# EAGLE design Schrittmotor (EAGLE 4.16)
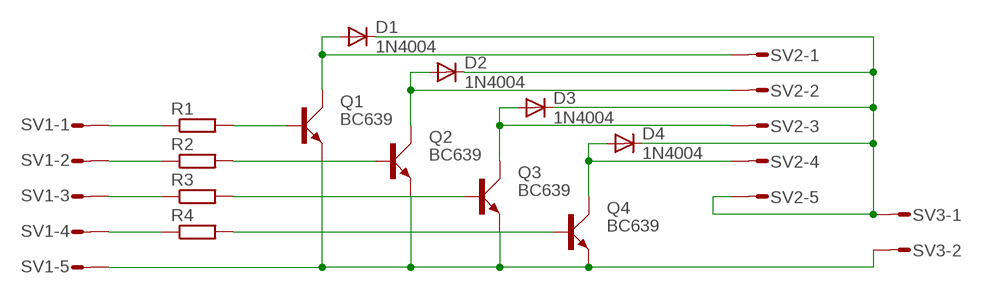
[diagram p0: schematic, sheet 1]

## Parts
D1  1N4004  [DO41-10]
D2  1N4004  [DO41-10]
D3  1N4004  [DO41-10]
D4  1N4004  [DO41-10]
Q1  BC639  [SOT54D]
Q2  BC639  [SOT54D]
Q3  BC639  [SOT54D]
Q4  BC639  [SOT54D]
R1  R-EU_0204/7  [0204/7]
R2  R-EU_0204/7  [0204/7]
R3  R-EU_0204/7  [0204/7]
R4  R-EU_0204/7  [0204/7]
SV1  L05P  [L05P]
SV2  L05P  [L05P]
SV3  L02P  [L02P]

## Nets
GND: Q1.E Q2.E Q3.E Q4.E SV1.5 SV3.2
N$1: R1.1 SV1.1
N$2: R2.1 SV1.2
N$3: R3.1 SV1.3
N$4: R4.1 SV1.4
N$5: Q1.B R1.2
N$7: Q2.B R2.2
N$9: Q3.B R3.2
N$11: Q4.B R4.2
N$12: D1.A Q1.C SV2.1
N$13: D2.A Q2.C SV2.2
N$14: D3.A Q3.C SV2.3
N$15: D4.A Q4.C SV2.4
UF: D1.C D2.C D3.C D4.C SV2.5 SV3.1

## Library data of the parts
D1-D4 = diode:1N4004: DIODE
Q1-Q4 = transistor-small-signal:BC639: NPN TRANSISTOR
R1-R4 = rcl:R-EU_: RESISTOR, European symbol
SV1 SV2 = con-amp-mt:L05P: AMP MT CONNECTOR
SV3 = con-amp-mt:L02P: AMP MT CONNECTOR

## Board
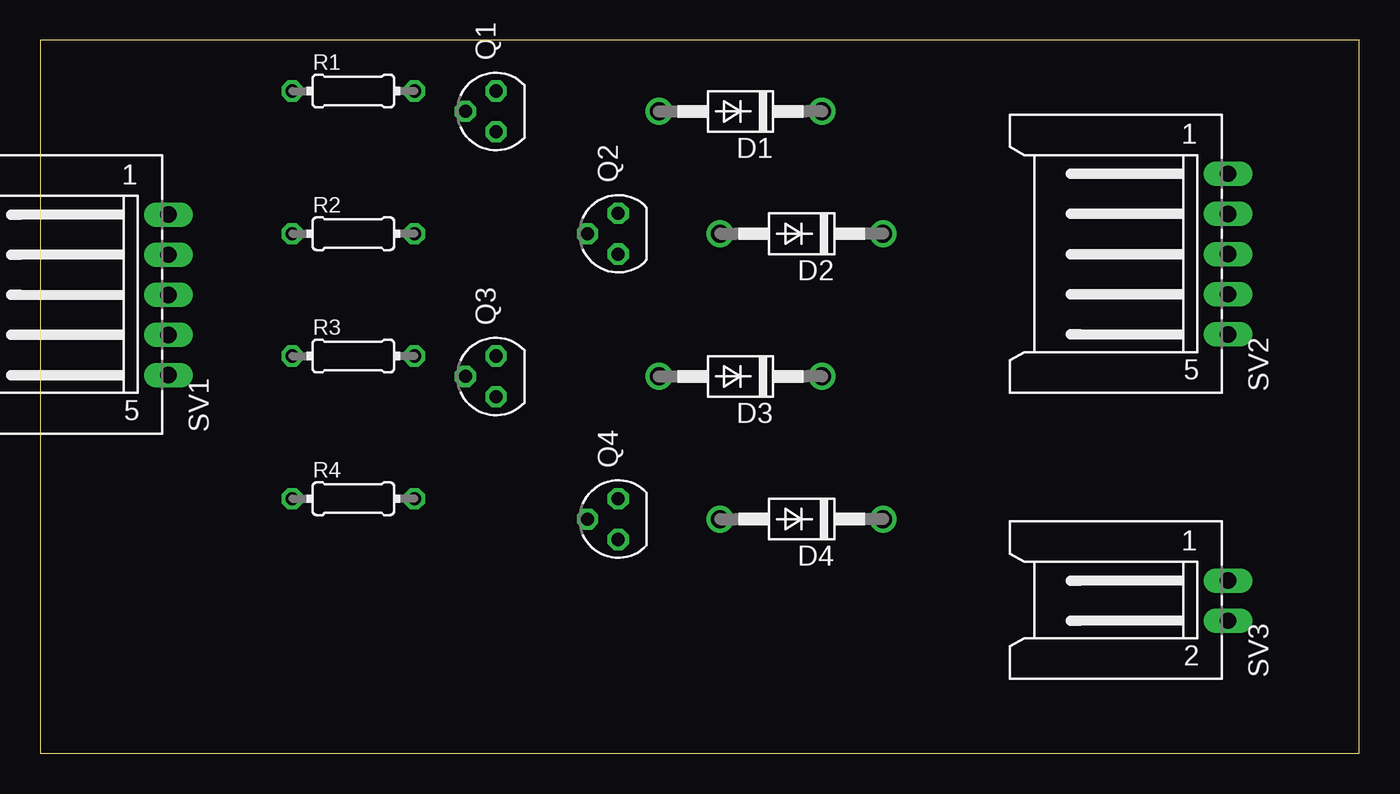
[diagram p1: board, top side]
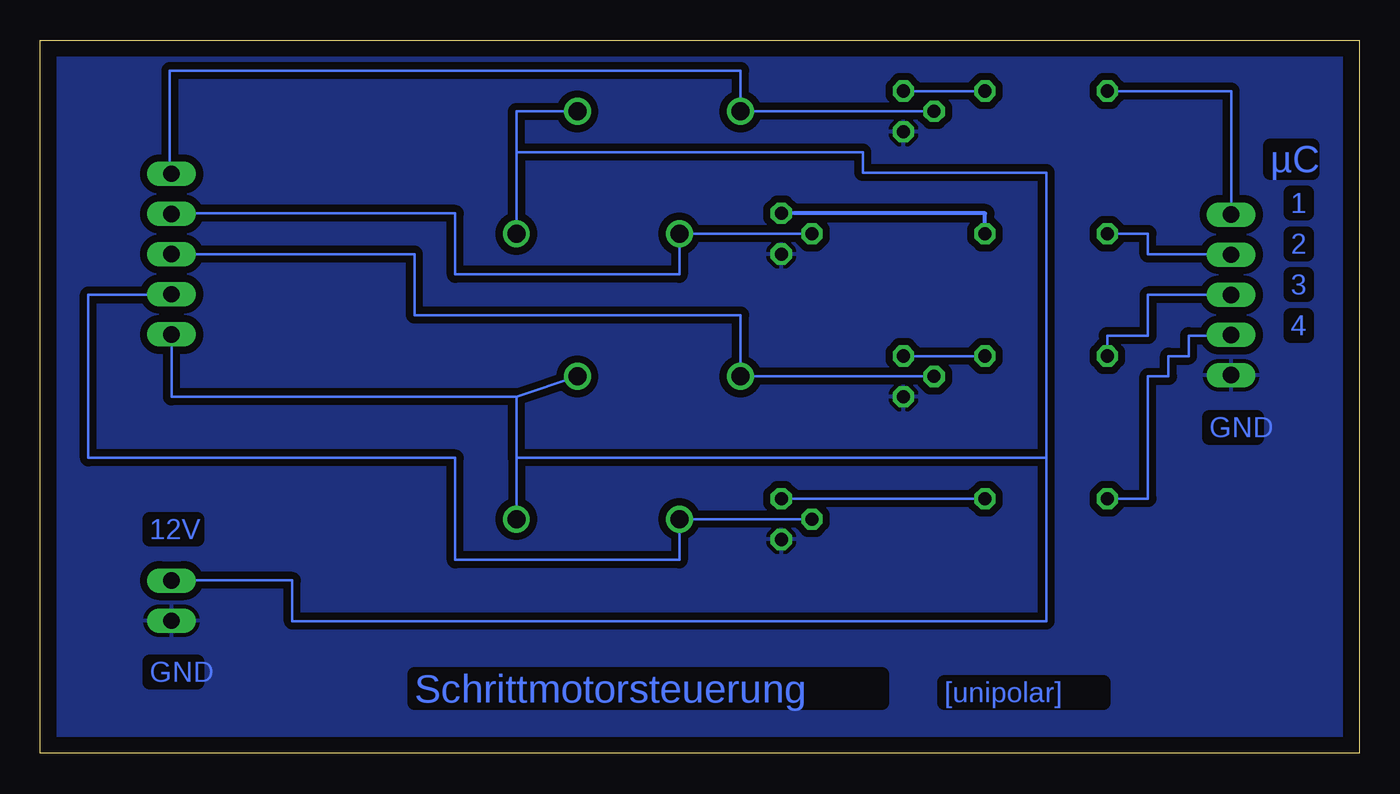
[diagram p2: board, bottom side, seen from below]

Size 82.22 x 44.44 mm. Coordinates in mm from the lower left corner, seen from the top.
Outline: 0,0 82.22,0 82.22,44.44 0,44.44 0,0
Copper layers (1*16): Top 0.035mm / dielectric 1.5mm / Bottom 0.035mm
Design rules "default": minimum track width 10mil, minimum drill 24mil, track to track 18mil, track to pad 18mil, pad to pad 10mil, via to via 10mil, smd to smd 8mil, copper to edge 40mil, drill to drill 8mil, minimum pad ring 10mil, minimum via ring 8mil, stop-mask expansion 4mil, vias tented up to drill 0mil, thermal gap 10mil

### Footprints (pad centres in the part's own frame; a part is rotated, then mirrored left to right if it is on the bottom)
DO41-10 = drill 1.118 round: A 5.08,0; C -5.08,0
SOT54D = drill 0.813 octagon: B 1.27,0; C 0,1.905; E -1.27,0
0204/7 = drill 0.813 octagon: 1 -3.81,0; 2 3.81,0
L05P = drill 1.016 long: 1 5,-6.25; 2 2.5,-6.25; 3 0,-6.25; 4 -2.5,-6.25; 5 -5,-6.25
L02P = drill 1.016 long: 1 1.25,-6.25; 2 -1.25,-6.25

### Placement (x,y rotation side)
D1  43.65,40 180 top
D2  47.46,32.38 180 top
D3  43.65,23.49 180 top
D4  47.46,14.6 180 top
Q1  28.41,40 90 top
Q2  36.03,32.38 90 top
Q3  28.41,23.49 90 top
Q4  36.03,14.6 90 top
R1  19.52,41.27 0 top
R2  19.52,32.38 0 top
R3  19.52,24.76 0 top
R4  19.52,15.87 0 top
SV1  1.74,28.57 90 top
SV2  67.78,31.11 90 top
SV3  67.78,9.52 90 top

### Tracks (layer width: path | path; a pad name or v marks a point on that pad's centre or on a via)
GND
  pour Bottom: -0.8,45.08 -0.8,-0.64 83.02,-0.64 83.02,45.08
N$1
  Bottom 0.152: SV1.1 7.99,41.27 R1.1
N$2
  Bottom 0.152: 7.99,31.11 13.17,31.11 13.17,32.38 R2.1
  Bottom 0.254: SV1.2 7.99,31.11
N$3
  Bottom 0.152: SV1.3 13.17,28.57 13.17,26.03 15.71,26.03 R3.1
N$4
  Bottom 0.152: 7.99,26.03 10.63,26.03 10.63,24.76 11.9,24.76 11.9,23.49 13.17,23.49 13.17,15.87 R4.1
  Bottom 0.254: 7.99,26.03 SV1.4
N$5
  Bottom 0.152: R1.2 Q1.B
N$7
  Bottom 0.254: R2.2 23.33,33.65 Q2.B
N$9
  Bottom 0.152: R3.2 Q3.B
N$11
  Bottom 0.152: R4.2 Q4.B
N$12
  Bottom 0.152: Q1.C D1.A 38.57,42.54 74.13,42.54 74.13,36.19
  Bottom 0.254: 74.13,36.19 74.03,36.19 SV2.1
N$13
  Bottom 0.152: Q2.C D2.A 42.38,29.84 56.35,29.84 56.35,33.65 74.03,33.65
  Bottom 0.254: 74.13,33.65 74.03,33.65 SV2.2
N$14
  Bottom 0.152: Q3.C D3.A 38.57,27.3 58.89,27.3 58.89,31.11 SV2.3
  Bottom 0.254: SV2.3 74.13,31.11
N$15
  Bottom 0.152: Q4.C D4.A 42.38,12.06 56.35,12.06 56.35,18.41 79.21,18.41 79.21,28.57 74.03,28.57
  Bottom 0.254: 74.03,28.57 SV2.4
UF
  Bottom 0.152: D1.C 52.54,40 D2.C 52.54,37.46 30.95,37.46 30.95,36.19 19.52,36.19 19.52,18.41 | 52.54,22.22 D3.C | 52.54,18.41 D4.C | 52.54,18.41 52.54,22.22 | 19.52,18.41 52.54,18.41 | SV2.5 74.03,22.22 52.54,22.22 | 19.52,18.41 19.52,8.25 66.51,8.25 66.51,10.79 74.03,10.79 SV3.1

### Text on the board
Bottom: µC | 1 | 2 | 3 | 4 | GND | 12V | GND | [unipolar] | Schrittmotorsteuerung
